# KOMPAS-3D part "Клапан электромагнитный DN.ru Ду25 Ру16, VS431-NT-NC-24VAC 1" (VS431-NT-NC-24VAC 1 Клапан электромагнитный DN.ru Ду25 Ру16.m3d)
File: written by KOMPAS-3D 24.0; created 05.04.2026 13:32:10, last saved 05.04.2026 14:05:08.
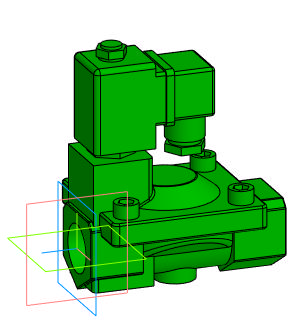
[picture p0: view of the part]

Document properties: Автор: artio; Полное имя файла: C:\Users\artio\OneDrive\Рабочий стол\Клапан электромагнитный DN.ru\VS431\VS431-NT-NC\VS431-NT-NC-24VAC\Ду25\VS431-NT-NC-24VAC 1 Клапан электромагнитный DN.ru Ду25 Ру16.m3d

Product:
- Body: Тело 1  | qty 1
    Масса: 1.729172
- Part/product: Клапан электромагнитный DN.ru Ду25 Ру16  | designation VS431-NT-NC-24VAC 1
    Масса: 1.267
    Раздел спецификации: Прочие изделия
    Примечание: D130-05509
    additional columns: ef56311e-7521-43dc-8291-0e6108b3d81d; artio; c; Шероховатость не задана; Да

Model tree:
1. Операция без истории:1

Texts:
  VS431-NT-NC-24VAC 1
